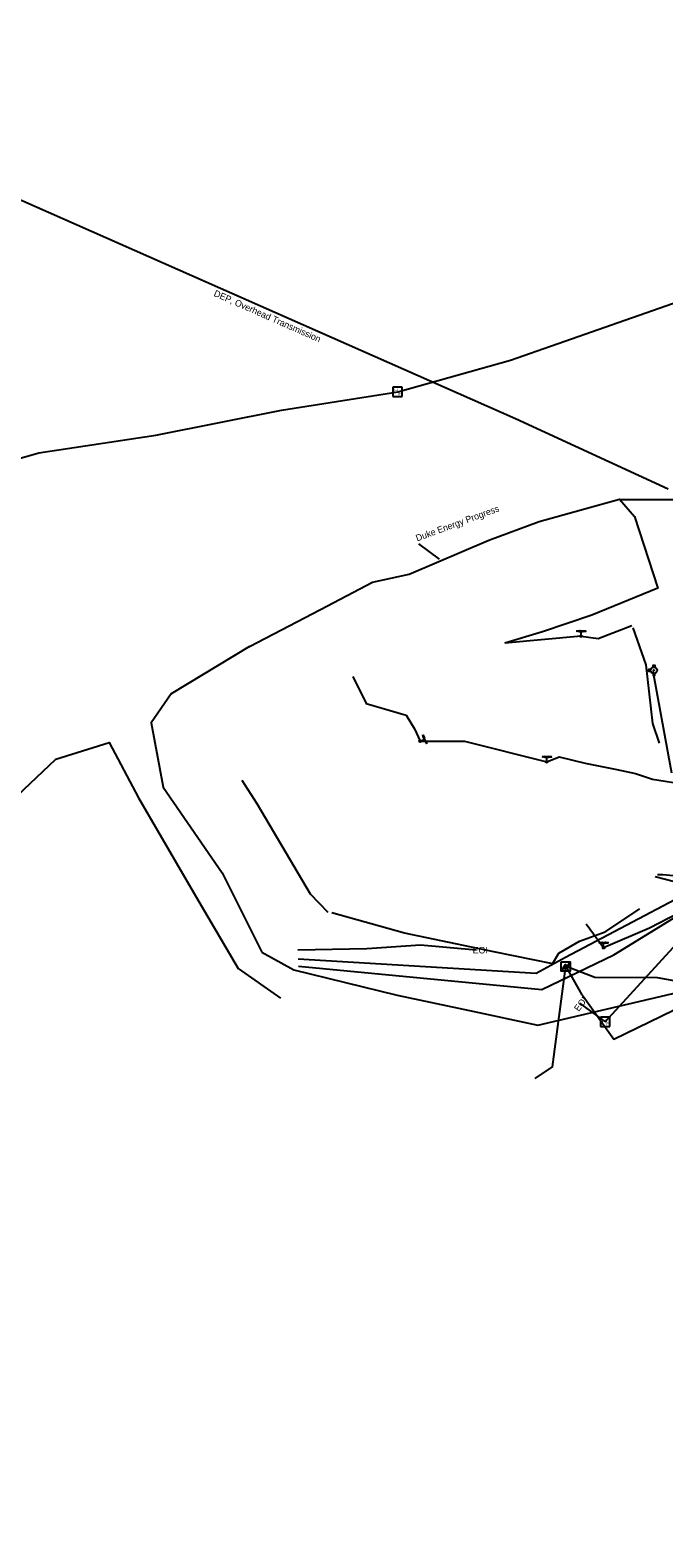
# Model space of a CAD drawing. Extents: x 2070721 to 2083340, y 729290 to 737883.
# Drawn here: x 2079796 to 2080183, y 733835 to 734755 of the extents above; entities that cross this region are included whole.
import ezdxf

# ---------------------------------------------------------------- set-up
doc = ezdxf.new("R2010")
doc.units = 0
for name, color, linetype in [('Exist Utilities Other Pole With Base Text', 7, 'Continuous'), ('Exist Utilities Other Unknown UG SUE LOS B', 7, 'Continuous'), ('Exist Utilities Power Change of Service SUE CELL', 7, 'Continuous'), ('Exist Utilities Power Transformer CELL', 7, 'Continuous'), ('Exist Utilities Power UG Cable SUE LOS B', 7, 'Continuous'), ('Exist Utilities Power UG Cable SUE LOS B Leader', 7, 'Continuous'), ('Exist Utilities Power UG Cable SUE LOS B Text', 7, 'Continuous'), ('Exist Utilities Power UG Cable SUE LOS C', 7, 'Continuous'), ('Exist Utilities Power UG Cable SUE LOS C Text', 7, 'Continuous'), ('Exist Utilities Telephone Change of Service SUE CELL', 7, 'Continuous'), ('Exist Utilities Telephone Hand Hole CELL', 7, 'Continuous'), ('Exist Utilities Telephone Hand Hole Text', 7, 'Continuous'), ('Exist Utilities Telephone UG Cable SUE LOS C', 7, 'Continuous'), ('Exist Utilities Telephone UG FO SUE LOS B', 7, 'Continuous'), ('Exist Utilities Telephone UG FO SUE LOS C', 7, 'Continuous'), ('Exist Utilities TV UG FO Cable SUE LOS C', 7, 'Continuous'), ('Exist Utilities Water Fire Hydrant CELL', 7, 'Continuous'), ('Exist Utilities Water UG Line SUE LOS B', 7, 'Continuous')]:
    doc.layers.add(name, color=color, linetype=linetype)

msp = doc.modelspace()

# ---------------------------------------------------------------- linework, layer by layer
at = {"layer": 'Exist Utilities Other Unknown UG SUE LOS B'}
msp.add_lwpolyline([(2079959.52, 734193.69), (2080001.7, 734194.52), (2080034.61, 734196.83), (2080068.68, 734193.69)], dxfattribs=at)
at = {"layer": 'Exist Utilities Power Change of Service SUE CELL'}
for p, q in [((2080135.86, 734388.37), (2080129.89, 734388.37)), ((2080132.72, 734385.28), (2080132.72, 734388.37)), ((2080132.72, 734388.37), (2080135.86, 734388.37)), ((2080132.72, 734385.28), (2080132.72, 734385.28)), ((2080034.29, 734321.15), (2080037.1, 734322.41)), ((2080034.29, 734321.15), (2080034.29, 734321.15)), ((2080038.38, 734319.55), (2080035.95, 734324.99)), ((2080037.1, 734322.41), (2080038.38, 734319.55)), ((2080114.82, 734311.57), (2080108.86, 734311.57)), ((2080111.69, 734308.48), (2080111.69, 734311.57)), ((2080111.69, 734311.57), (2080114.82, 734311.57)), ((2080111.69, 734308.48), (2080111.69, 734308.48))]:
    msp.add_line(p, q, dxfattribs=at)
for points in [[(2080129.89, 734388.37), (2080131.87, 734388.71), (2080131.45, 734388.37), (2080131.83, 734388.06)], [(2080135.86, 734388.37), (2080133.89, 734388.02), (2080134.31, 734388.37), (2080133.92, 734388.67)], [(2080035.95, 734324.99), (2080037.07, 734323.33), (2080036.58, 734323.58), (2080036.46, 734323.1)], [(2080038.38, 734319.55), (2080037.27, 734321.21), (2080037.75, 734320.96), (2080037.87, 734321.44)], [(2080108.86, 734311.57), (2080110.83, 734311.91), (2080110.41, 734311.57), (2080110.79, 734311.26)], [(2080114.82, 734311.57), (2080112.85, 734311.22), (2080113.27, 734311.57), (2080112.89, 734311.87)]]:
    msp.add_lwpolyline(points, close=True, dxfattribs=at)
for centre in [(2080132.72, 734385.28), (2080034.29, 734321.15), (2080111.69, 734308.48)]:
    msp.add_circle(centre, 0.517, dxfattribs=at)
at = {"layer": 'Exist Utilities Power Transformer CELL'}
msp.add_line((2080123.44, 734183.74), (2080123.44, 734183.74), dxfattribs=at)
msp.add_lwpolyline([(2080120.6, 734186.35), (2080126.15, 734186.35), (2080126.15, 734180.8), (2080120.6, 734180.8)], close=True, dxfattribs=at)
for points in [[(2080120.6, 734180.8), (2080123.24, 734184.74), (2080123.87, 734182.53), (2080126.15, 734186.35)], [(2080120.67, 734180.8), (2080123.24, 734184.53), (2080123.83, 734182.35), (2080126.15, 734186.2)]]:
    msp.add_lwpolyline(points, dxfattribs=at)
at = {"layer": 'Exist Utilities Power UG Cable SUE LOS B'}
msp.add_line((2080133.41, 734166.28), (2080123.55, 734183.66), dxfattribs=at)
for points in [[(2079930.03, 734379.03), (2079973.5, 734401.57), (2080005.21, 734418.36), (2080027.53, 734423.19), (2080076.32, 734443.97), (2080107.09, 734455.28), (2080156.31, 734468.93), (2080165.35, 734458.46), (2080179.56, 734414.66), (2080139.33, 734398.19), (2080109.12, 734387.94), (2080086.12, 734381.02)], [(2080156.43, 734468.74), (2080190.75, 734468.74), (2080225.32, 734462.79), (2080232.03, 734473.2), (2080247.47, 734473.2), (2080279.52, 734463.97), (2080291.1, 734455.07), (2080294.67, 734448.18)], [(2080132.72, 734385.28), (2080143.11, 734383.81), (2080163.79, 734391.8)], [(2080180.65, 734319.97), (2080176.58, 734332.03), (2080172.45, 734367.8), (2080164.56, 734390.43)], [(2079930.02, 734378.99), (2079882.12, 734350.06), (2079869.95, 734332.5), (2079877.26, 734293.02), (2079913.22, 734240.74), (2079937.52, 734192.32)], [(2079993.15, 734360.7), (2080001.25, 734344.21), (2080025.77, 734337.16), (2080030.9, 734328.74), (2080034.29, 734321.15)], [(2080111.69, 734308.48), (2080119.26, 734311.71), (2080135.22, 734307.67), (2080154.56, 734303.8), (2080166.01, 734301.54), (2080176.37, 734298.05), (2080196.98, 734294.69), (2080210.47, 734255.68), (2080223.19, 734226.04), (2080229.85, 734192.73), (2080230.05, 734182.23)], [(2079978.2, 734216.61), (2079967.4, 734227.75), (2079934.73, 734282.87), (2079925.44, 734297.1)], [(2080116.92, 734185.79), (2080115.37, 734185.19), (2080079.38, 734192.5), (2080024.85, 734203.9), (2079980.32, 734216.35)], [(2080115.35, 734185.21), (2080119.22, 734191.73), (2080131.84, 734199.07), (2080147.42, 734204.74), (2080168.6, 734218.76)], [(2079937.52, 734192.32), (2079957.19, 734181.58), (2080020.32, 734166.12), (2080064.52, 734156.78), (2080106.22, 734147.77), (2080188.06, 734166.87), (2080235.43, 734179.74)], [(2080225.42, 734168.33), (2080179.4, 734176.66), (2080141.16, 734176.91), (2080123.55, 734183.66)], [(2080133.41, 734166.28), (2080133.92, 734165.53), (2080152.74, 734139.3), (2080189.19, 734157.01), (2080229.69, 734182.03)]]:
    msp.add_lwpolyline(points, dxfattribs=at)
at = {"layer": 'Exist Utilities Power UG Cable SUE LOS B Leader'}
msp.add_line((2080046.09, 734432.28), (2080033.5, 734441.82), dxfattribs=at)
at = {"layer": 'Exist Utilities Power UG Cable SUE LOS C'}
msp.add_line((2080132.72, 734385.28), (2080086.11, 734381.03), dxfattribs=at)
for points in [[(2078562.59, 735087.36), (2079031.08, 734900.74), (2079505.61, 734777.36), (2080092.6, 734518.21), (2080186.05, 734475.29)], [(2079521.46, 733782.07), (2079612.63, 733995.04), (2079660.37, 734083.05), (2079722.69, 734198.01), (2079772.2, 734273.08), (2079811.65, 734310.23), (2079844.14, 734320.29), (2079862.09, 734286.62), (2079897.07, 734226.66), (2079923.09, 734182.44), (2079949.03, 734164.15)], [(2080034.29, 734321.15), (2080061.44, 734321.15), (2080111.69, 734308.48)], [(2080104.68, 734115.2), (2080115.28, 734122.27), (2080123.44, 734183.74)]]:
    msp.add_lwpolyline(points, dxfattribs=at)
at = {"layer": 'Exist Utilities Telephone Change of Service SUE CELL'}
for p, q in [((2080149.59, 734198.08), (2080143.62, 734198.08)), ((2080146.45, 734195), (2080146.45, 734198.08)), ((2080146.45, 734198.08), (2080149.59, 734198.08)), ((2080146.45, 734195), (2080146.45, 734195))]:
    msp.add_line(p, q, dxfattribs=at)
for points in [[(2080143.62, 734198.08), (2080145.59, 734198.43), (2080145.17, 734198.08), (2080145.56, 734197.78)], [(2080149.59, 734198.08), (2080147.61, 734197.74), (2080148.03, 734198.08), (2080147.65, 734198.39)]]:
    msp.add_lwpolyline(points, close=True, dxfattribs=at)
msp.add_circle((2080146.45, 734195), 0.517, dxfattribs=at)
at = {"layer": 'Exist Utilities Telephone Hand Hole CELL'}
for p, q in [((2080017.67, 734537.36), (2080017.67, 734531.64)), ((2080023.39, 734537.36), (2080017.67, 734537.36)), ((2080017.67, 734531.64), (2080023.39, 734531.64)), ((2080020.53, 734534.5), (2080020.53, 734534.5)), ((2080023.39, 734531.64), (2080023.39, 734537.36)), ((2080144.66, 734152.66), (2080144.66, 734146.93)), ((2080150.39, 734152.66), (2080144.66, 734152.66)), ((2080150.39, 734146.93), (2080150.39, 734152.66)), ((2080144.66, 734146.93), (2080150.39, 734146.93)), ((2080147.53, 734149.79), (2080147.53, 734149.79))]:
    msp.add_line(p, q, dxfattribs=at)
at = {"layer": 'Exist Utilities Telephone UG Cable SUE LOS C'}
msp.add_lwpolyline([(2080179.48, 734239.75), (2080182.79, 734239.75), (2080204.44, 734237.74), (2080223.27, 734244.14), (2080227.06, 734249.97), (2080225.75, 734270.22), (2080228.23, 734298.53), (2080237.75, 734333.83), (2080246.14, 734355.32), (2080258.39, 734393.6), (2080274.22, 734418.19), (2080320.87, 734477.75), (2080344.36, 734497.56), (2080358.62, 734490.18), (2080387.98, 734454.99)], dxfattribs=at)
at = {"layer": 'Exist Utilities Telephone UG FO SUE LOS B'}
msp.add_line((2080147.47, 734150), (2080131.9, 734161.22), dxfattribs=at)
for points in [[(2079745.48, 734481.51), (2079801.23, 734497.35), (2079872.83, 734508.05), (2079949.65, 734523.37), (2080020.61, 734534.5), (2080089.55, 734553.89), (2080188.62, 734588.57), (2080251.31, 734612.62), (2080291.78, 734621.68), (2080331.66, 734636.74), (2080409.13, 734669.6), (2080483.75, 734695.04), (2080565.61, 734724.43), (2080648.3, 734753.97), (2080723.36, 734781.19), (2080819.84, 734816.74), (2080898.17, 734842.61), (2080939.09, 734839.81), (2081012.97, 734869.95)], [(2079959.83, 734188.33), (2080105.23, 734179.43), (2080123.21, 734189.25), (2080234.98, 734248.06)], [(2080222.28, 734231.61), (2080174.53, 734207.04), (2080146.45, 734195)]]:
    msp.add_lwpolyline(points, dxfattribs=at)
at = {"layer": 'Exist Utilities Telephone UG FO SUE LOS C'}
for p, q in [((2080147.53, 734149.79), (2080222.17, 734231.63)), ((2080146.45, 734195), (2080135.76, 734209.46))]:
    msp.add_line(p, q, dxfattribs=at)
msp.add_lwpolyline([(2080225.43, 734233.87), (2080195.29, 734233.87), (2080178.12, 734238.44)], dxfattribs=at)
at = {"layer": 'Exist Utilities TV UG FO Cable SUE LOS C'}
msp.add_lwpolyline([(2079959.93, 734183.76), (2080108.68, 734169.55), (2080152.84, 734190.77), (2080228.33, 734237.2), (2080232.67, 734236.44)], dxfattribs=at)
at = {"layer": 'Exist Utilities Water Fire Hydrant CELL'}
msp.add_line((2080177.24, 734364.47), (2080177.24, 734364.47), dxfattribs=at)
for points in [[(2080175.33, 734364.98), (2080174.04, 734364.98), (2080174.04, 734363.96), (2080175.33, 734363.96)], [(2080176.73, 734366.38), (2080176.73, 734367.67), (2080177.75, 734367.67), (2080177.75, 734366.36)], [(2080176.73, 734362.56), (2080176.73, 734361.27), (2080177.75, 734361.27), (2080177.75, 734362.58)]]:
    msp.add_lwpolyline(points, dxfattribs=at)
for radius in [1.98, 0.243]:
    msp.add_circle((2080177.24, 734364.47), radius, dxfattribs=at)
at = {"layer": 'Exist Utilities Water UG Line SUE LOS B'}
msp.add_lwpolyline([(2080176.61, 734363.96), (2080186.04, 734312.89), (2080188.09, 734301.77)], dxfattribs=at)

# ---------------------------------------------------------------- texts
at = {"layer": 'Exist Utilities Other Pole With Base Text'}
msp.add_text('EOI', height=4, dxfattribs=at).set_placement((2080066.49, 734191.55))
at = {"layer": 'Exist Utilities Power UG Cable SUE LOS B Text'}
msp.add_text('Duke Energy Progress', height=4, rotation=20.18977, dxfattribs=at).set_placement((2080032.54, 734443.16))
at = {"layer": 'Exist Utilities Power UG Cable SUE LOS C Text'}
msp.add_text('DEP, Overhead Transmission ', height=4, rotation=336.17811, dxfattribs=at).set_placement((2079907.78, 734593.25))
at = {"layer": 'Exist Utilities Telephone Hand Hole CELL'}
for p in [(2080018.45, 734533.91), (2080021.02, 734532.44), (2080145.44, 734149.2), (2080148.01, 734147.74)]:
    msp.add_text('H', height=2.5, dxfattribs=at).set_placement(p)
at = {"layer": 'Exist Utilities Telephone Hand Hole Text'}
msp.add_text('EOI', height=4, rotation=53.16319, dxfattribs=at).set_placement((2080131.29, 734155.78))

doc.saveas('drawing.dxf')
